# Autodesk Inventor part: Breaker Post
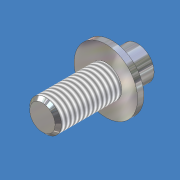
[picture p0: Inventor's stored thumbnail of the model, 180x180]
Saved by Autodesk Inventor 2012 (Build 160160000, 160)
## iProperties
Shininess: 64.0
Angle Display Precision: 2
Document Length Units: 11272
Document Angle Units: 11279
Document Time Units: 11290
Document Mass Units: 11286
Document Length Units Precision: 3
Document Angle Units Precision: 2
Compacted: True
Created: 2004-01
Part Number: Breaker Post
Material: Steel, Mild
Document SubType Name: Modeling
Designer: t8558es
Density: 1 g/cm^3
Density: 0.0
Volumn: 0.0
Area: 0.0
PropertySet Name: Model Information
Control State: 0
Master: False
Checked Out: False
Author: t8558es
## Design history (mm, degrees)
sketch "Sketch1"
  geometry: C1 r 6.35 at (0, 0); 1 further point
  constraints: 1 centre point, 1 coincident, 1 other
  dimensions: "d0" = 12.7 diameter of C1
extrude "Extrusion1" new body sketch "Sketch1" distance "d1" = 1.27; taper "d2" = 0 deg
sketch "Sketch2"
  geometry: C1 r 6.35 at (0, 0) reference; C2 r 3.175 at (0, 0)
  constraints: 1 centre point, 1 coincident
  dimensions: "d3" = 6.35 diameter of C2
extrude "Extrusion2" join sketch "Sketch2" distance "d4" = 12.7; taper "d5" = 0 deg
chamfer "Chamfer1" distance "d6" = 0.635; stored, may be unused: second distance "d7" = 0.635, angle "d13" = 45 deg
thread "Thread1" dims "d8" = 25.4, "d9" = 0
sketch "Sketch3"
  geometry: C1 r 6.35 at (0, 0) reference; C2 r 3.302 at (0, 0)
  constraints: 1 centre point, 1 coincident
  dimensions: "d10" = 6.604 diameter of C2
extrude "Extrusion3" join sketch "Sketch3" distance "d11" = 5.08; taper "d12" = 0 deg
body "Solid1"
